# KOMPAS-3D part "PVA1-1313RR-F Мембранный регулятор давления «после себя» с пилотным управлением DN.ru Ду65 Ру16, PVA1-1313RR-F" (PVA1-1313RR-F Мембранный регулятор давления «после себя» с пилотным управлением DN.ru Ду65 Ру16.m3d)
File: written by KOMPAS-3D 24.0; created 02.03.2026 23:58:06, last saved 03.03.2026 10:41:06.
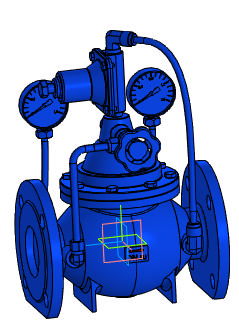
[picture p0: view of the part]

Document properties: Автор: R2D2; Полное имя файла: PVA1-1313RR-F PVA1-1313RR-F Мембранный регулятор давления «после себя» с пилотным управлением DN.ru Ду65 Ру16.cdw

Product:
- Part/product: PVA1-1313RR-F Мембранный регулятор давления «после себя» с пилотным управлением DN.ru Ду65 Ру16  | designation PVA1-1313RR-F
    Масса: 10
    Раздел спецификации: Прочие изделия
    Форматы листов документа: A3
    Примечание: D230-10618
    additional columns: D230-10618

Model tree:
1. Операция без истории:2

Expressions: PVA1-1313RR-F
Referenced files in C:\Program Files\ASCON\KOMPAS-3D v24\Libs\Pipeline\: StylesTemplate.a3d, TemplateHPH, InsulationStylesTemplate.a3d, Insulation
Referenced files in C:\Program Files\ASCON\KOMPAS-3D v24\Templates\: Констр. чертеж А3 гориз. перв. лист.cdt
Referenced files in E:\Работа\Зайцев\PVA1-1313RR-F Мембранный регулятор давления «после себя» с пилотным управлением DN.ru Ду50-200 Ру16\DN65\исходные материалы\: 
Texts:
  Отводы ГОСТ 17375-2001
  Констр. чертеж А3 гориз. перв. лист.cdt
